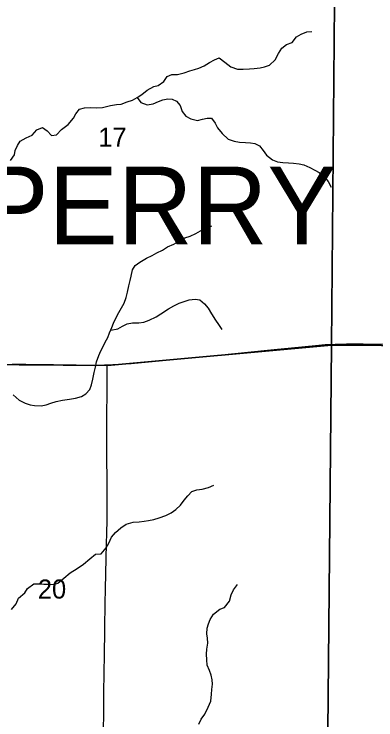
# Model space of a CAD drawing. Extents: x 1874609 to 2204689, y 815661 to 1281160.
# Drawn here: x 2052242 to 2056444, y 1036541 to 1044730 of the extents above; entities that cross this region are included whole.
import ezdxf

# ---------------------------------------------------------------- set-up
doc = ezdxf.new("R2010")
doc.units = 0
for name, color, linetype in [('GM_X_Minor_River', 7, 'Continuous'), ('GM_X_Section', 7, 'Continuous'), ('GM_X_Section_Text', 7, 'Continuous'), ('GM_X_Township_Road', 7, 'Continuous'), ('GM_X_Township_Text', 7, 'Continuous'), ('GM_X_US_Route', 7, 'Continuous')]:
    doc.layers.add(name, color=color, linetype=linetype)

msp = doc.modelspace()

# ---------------------------------------------------------------- linework, layer by layer
at = {"layer": 'GM_X_Minor_River'}
for points in [[(2052507.5, 1043385.7), (2052573.5, 1043415.9), (2052625.8, 1043374), (2052678, 1043320.1), (2052736, 1043328.3), (2052792, 1043390.6), (2052871.9, 1043448.9), (2052933.8, 1043523.2), (2052959.7, 1043573.4), (2053003.6, 1043625.6), (2053059.6, 1043641.8), (2053129.7, 1043646), (2053199.8, 1043642.2), (2053269.9, 1043646.4), (2053364, 1043668.8), (2053430.1, 1043683), (2053484.1, 1043685.2), (2053556.2, 1043711.4), (2053616.2, 1043731.6), (2053670.2, 1043761.8), (2053724.2, 1043798.1), (2053786.1, 1043848.3), (2053864.1, 1043888.7), (2053916.2, 1043902.8), (2053980.1, 1043949.1), (2054022, 1044007.3), (2054076, 1044029.5), (2054142.1, 1044029.7), (2054218.2, 1044048), (2054284.2, 1044070.2), (2054338.3, 1044086.4), (2054388.3, 1044102.6), (2054448.3, 1044128.8), (2054512.3, 1044169.1), (2054570.3, 1044201.3), (2054624.3, 1044221.5), (2054688.5, 1044171.6), (2054760.8, 1044119.8), (2054837, 1044091.9), (2054901.1, 1044090.1), (2054975.2, 1044096.3), (2055029.3, 1044100.5), (2055099.4, 1044106.8), (2055149.4, 1044118.9), (2055209.5, 1044137.1), (2055273.4, 1044199.4), (2055313.2, 1044271.7), (2055353.1, 1044333.9), (2055407, 1044378.1), (2055471.1, 1044402.4), (2055523, 1044466.6), (2055575, 1044498.8), (2055641, 1044525.1), (2055699.1, 1044527.3)], [(2053670.2, 1043761.8), (2053714.4, 1043703.9), (2053786.6, 1043678), (2053858.7, 1043690.3), (2053920.7, 1043716.5), (2053970.7, 1043734.7), (2054028.8, 1043748.9), (2054078.9, 1043745), (2054129, 1043721.2), (2054171.2, 1043669.2), (2054195.5, 1043599.2), (2054237.7, 1043545.2), (2054293.9, 1043515.3), (2054372, 1043497.5), (2054430.1, 1043509.7), (2054486.1, 1043523.9), (2054536.2, 1043522), (2054578.4, 1043466.1), (2054606.6, 1043412.1), (2054660.9, 1043344.1), (2054727.2, 1043278.2), (2054799.4, 1043256.4), (2054861.5, 1043244.5), (2054931.6, 1043240.8), (2054987.7, 1043236.9), (2055039.8, 1043229.1), (2055094, 1043203.2), (2055136.2, 1043147.2), (2055174.4, 1043093.2), (2055244.7, 1043037.4), (2055302.9, 1043017.5), (2055365, 1043007.7), (2055429.1, 1043003.9), (2055487.2, 1043000), (2055553.3, 1042992.2), (2055607.4, 1042980.4), (2055675.6, 1042950.5), (2055733.8, 1042920.6), (2055784, 1042892.7), (2055842.2, 1042844.8), (2055890.4, 1042788.9), (2055926.7, 1042722.9)], [(2052200.1, 1043032.2), (2052246, 1043098.4), (2052253.9, 1043148.5), (2052283.7, 1043204.7), (2052311.6, 1043254.9), (2052381.6, 1043295.2), (2052451.6, 1043325.4), (2052507.5, 1043385.7)], [(2052230.1, 1040313.6), (2052302.4, 1040249.7), (2052370.6, 1040217.9), (2052430.8, 1040198), (2052480.9, 1040190.2), (2052555, 1040186.4), (2052613, 1040196.6), (2052669.1, 1040214.8), (2052731.1, 1040235), (2052805.2, 1040251.3), (2052887.3, 1040263.5), (2052957.3, 1040273.8), (2053025.4, 1040294), (2053077.4, 1040324.2), (2053123.3, 1040376.4), (2053143.2, 1040430.6), (2053155, 1040492.7), (2053170.8, 1040570.9), (2053186.6, 1040635.1), (2053200.5, 1040697.2), (2053228.3, 1040769.4), (2053250.2, 1040821.6), (2053278.1, 1040873.7), (2053299.9, 1040923.9), (2053329.8, 1040978.1), (2053351.7, 1041032.2), (2053377.6, 1041094.4), (2053397.4, 1041144.6), (2053425.3, 1041200.8), (2053459.2, 1041267), (2053491.1, 1041323.2), (2053521, 1041375.3), (2053542.8, 1041441.5), (2053560.6, 1041505.7), (2053576.4, 1041575.8), (2053590.3, 1041638), (2053600.2, 1041690.1), (2053618, 1041764.3), (2053647.9, 1041814.5), (2053703.8, 1041852.7), (2053781.8, 1041897), (2053845.8, 1041929.2), (2053901.8, 1041959.5), (2053965.8, 1041991.7), (2054025.8, 1042030), (2054095.8, 1042062.2), (2054151.8, 1042092.5), (2054223.8, 1042134.7), (2054285.8, 1042155), (2054351.8, 1042185.2), (2054407.8, 1042215.4), (2054475.9, 1042247.7), (2054537.9, 1042273.9)], [(2053364.6, 1041063.2), (2053445.7, 1041076.6), (2053501.7, 1041110.8), (2053555.7, 1041137), (2053615.8, 1041147.2), (2053691.9, 1041149.5), (2053747.9, 1041157.7), (2053812, 1041177.9), (2053892, 1041218.2), (2053946, 1041252.4), (2054033.9, 1041310.8), (2054097.9, 1041345), (2054157.9, 1041375.3), (2054207.9, 1041391.4), (2054276, 1041413.7), (2054344.1, 1041423.9), (2054400.2, 1041416), (2054454.4, 1041370.1), (2054496.6, 1041318.2), (2054536.8, 1041254.2), (2054583.1, 1041180.2), (2054615.3, 1041128.2), (2054655.6, 1041072.2)], [(2052701.3, 1038111.3), (2052751.3, 1038129.5), (2052819.2, 1038185.8), (2052895.2, 1038246.1), (2052973.1, 1038296.5), (2053049.1, 1038348.8), (2053121, 1038411.1), (2053187, 1038463.4), (2053255.1, 1038469.6), (2053313, 1038537.9), (2053340.8, 1038592.1), (2053374.7, 1038660.3), (2053418.6, 1038716.5), (2053480.5, 1038768.8), (2053544.5, 1038811), (2053626.6, 1038835.3), (2053696.6, 1038837.6), (2053752.7, 1038845.8), (2053802.8, 1038853.9), (2053866.8, 1038866.1), (2053928.9, 1038886.3), (2054002.9, 1038914.6), (2054064.9, 1038944.9), (2054120.9, 1038983.1), (2054174.8, 1039033.3), (2054216.7, 1039091.6), (2054260.6, 1039141.8), (2054306.5, 1039192), (2054364.6, 1039212.2), (2054428.6, 1039218.4), (2054500.7, 1039238.7), (2054562.7, 1039262.9)], [(2052213.4, 1037821.3), (2052265.3, 1037889.6), (2052295.2, 1037951.8), (2052367.1, 1038016.1), (2052397, 1038066.3), (2052470.9, 1038118.6), (2052537, 1038118.8), (2052587.1, 1038115), (2052639.2, 1038115.1), (2052701.3, 1038111.3)], [(2054790.6, 1038049.5), (2054836.5, 1038111.8)], [(2054388.5, 1036491.7), (2054416.4, 1036547.9), (2054456.3, 1036608.1), (2054498.1, 1036690.4), (2054526, 1036758.6), (2054533.8, 1036838.7), (2054539.6, 1036892.8), (2054545.4, 1036957), (2054543.3, 1037007), (2054531.1, 1037061.1), (2054510.9, 1037113.1), (2054486.7, 1037177.2), (2054480.5, 1037239.2), (2054478.3, 1037305.3), (2054480.1, 1037361.4), (2054492, 1037431.6), (2054487.8, 1037487.7), (2054481.6, 1037537.8), (2054485.4, 1037603.9), (2054499.3, 1037654), (2054521.2, 1037706.2), (2054557.1, 1037768.4), (2054633, 1037824.7), (2054685, 1037846.9), (2054744.9, 1037919.2), (2054764.7, 1037993.4), (2054790.6, 1038049.5)]]:
    msp.add_lwpolyline(points, dxfattribs=at)
at = {"layer": 'GM_X_Section'}
for points in [[(2050900.3, 1046015), (2053522, 1045972.2), (2055974.7, 1046182.9), (2055929.2, 1040887.8), (2053326.5, 1040652.5), (2050755, 1040673.6)], [(2055974.7, 1046182.9), (2061181.9, 1046137), (2061162.3, 1040854), (2055929.2, 1040887.8)], [(2050755, 1040673.6), (2053326.5, 1040652.5), (2055929.2, 1040887.8), (2055877.6, 1035592.6), (2053260.4, 1035519.5), (2050614.9, 1035534.3)], [(2055929.2, 1040887.8), (2061162.3, 1040854), (2061170.7, 1035567.1), (2055877.6, 1035592.6)]]:
    msp.add_lwpolyline(points, close=True, dxfattribs=at)
at = {"layer": 'GM_X_Township_Road'}
msp.add_lwpolyline([(2053282.1, 1036461.3), (2053283.6, 1036576), (2053286.5, 1036838.4), (2053288.7, 1037100.8), (2053291.9, 1037281.2), (2053295.2, 1037592.8), (2053301.1, 1037904.5), (2053304.8, 1038052), (2053309.2, 1038248.7), (2053312.8, 1038406.4), (2053317.1, 1038594), (2053319.5, 1038697.3), (2053323.5, 1038871.4), (2053324.1, 1038969.8), (2053323.9, 1039215.9), (2053320.3, 1039691.6), (2053320.4, 1040052.4), (2053320.3, 1040150.8), (2053321.8, 1040265.6), (2053324.1, 1040446), (2053324.2, 1040557), (2053324.3, 1040639.5), (2053324.3, 1040660.5)], dxfattribs=at)
at = {"layer": 'GM_X_US_Route'}
msp.add_lwpolyline([(2052224.7, 1040671.3), (2052536.2, 1040665.5), (2052700.3, 1040663.3), (2052847.9, 1040661.9), (2052962.7, 1040659.8), (2053143.2, 1040657.4), (2053225.3, 1040658.2), (2053293.1, 1040659.8), (2053324.3, 1040660.5), (2053455, 1040666.7), (2053602.4, 1040677.1), (2053929, 1040708.5), (2054271.9, 1040741.7), (2054614.9, 1040773.5), (2055186.2, 1040829.8), (2055300.4, 1040841.4), (2055463.8, 1040857.8), (2055741.3, 1040885.9), (2055855.6, 1040895.1), (2055970.2, 1040900.3), (2056101.3, 1040903.5), (2056298.2, 1040903.5), (2056626.4, 1040901.5)], dxfattribs=at)

# ---------------------------------------------------------------- texts
at = {"layer": 'GM_X_Section_Text'}
for s, p in [('17', (2053220.5, 1043192)), ('20', (2052518.7, 1037948.8))]:
    msp.add_text(s, height=221, rotation=0.00001, dxfattribs=at).set_placement(p)
at = {"layer": 'GM_X_Township_Text'}
msp.add_text('PERRY', height=900, rotation=0.00001, dxfattribs=at).set_placement((2051840.8, 1042060.2))

doc.saveas('drawing.dxf')
